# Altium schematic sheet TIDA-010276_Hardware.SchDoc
size 431 x 279 mm; Date: Not shown in title block; ApprovedBy: Not shown in title block; CheckedBy: Not shown in title block; Author: Not shown in title block; CompanyName: Not shown in title block; DrawnBy: Jenson Fang; Engineer: Jenson Fang; Organization: Not shown in title block; Address1: Not shown in title block; Address2: Not shown in title block; Address3: Not shown in title block; Address4: Not shown in title block; DocumentNumber: 3; Revision: Use project parameter SCH_Rev; SheetNumber: 6; SheetTotal: 6; PageSetup: Record=PageOptions¦CenterHorizontal=True¦CenterVertical=True¦PrintScale=1.00¦XCorrection=1.00¦YCorrection=1.00¦PrintKind=0¦BorderSize=5000000¦LeftOffset=0¦BottomOffset=0¦Orientation=2¦PaperLength=1000¦PaperWidth=1000¦Scale=100¦PaperSource=15¦PrintQuality=600¦MediaType=1¦DitherType=10¦PaperKind=Letter¦PrintScaleMode=1
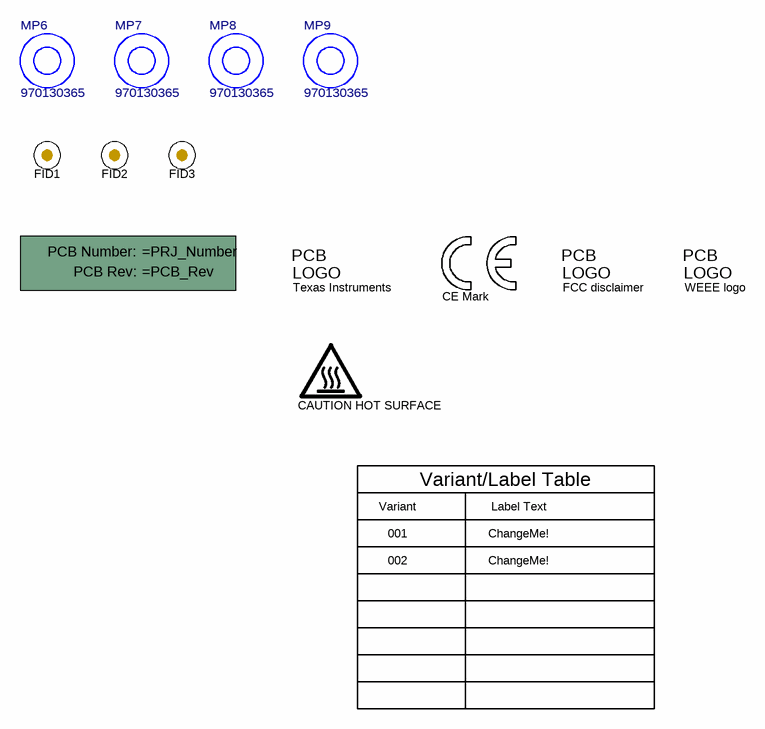
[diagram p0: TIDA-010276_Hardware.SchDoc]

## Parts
!PCB1  Printed Circuit Board  (value not drawn)  (mechanical)
FID1  Fiducial  [Fiducial10-20]  (value not drawn)
FID2  Fiducial  [Fiducial10-20]  (value not drawn)
FID3  Fiducial  [Fiducial10-20]  (value not drawn)
Logo1  CE Mark  [CE_Mark_5mm]  (no BOM)
Logo2  Texas Instruments  [TI_Stacked_Overlay_Small]  (no BOM)
Logo3  FCC disclaimer  [FCC_disclaimer]  (no BOM)
Logo4  WEEE logo  [WEEE_Minimum]  (no BOM)
LOGO5  CAUTION HOT SURFACE  [IEC_HotSurface_Small]  (no BOM)
MP6  970130365  [FP-970130365_SPCAER_M3-MFG]
MP7  970130365  [FP-970130365_SPCAER_M3-MFG]
MP8  970130365  [FP-970130365_SPCAER_M3-MFG]
MP9  970130365  [FP-970130365_SPCAER_M3-MFG]

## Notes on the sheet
- Variant
- Variant/Label Table
- Label Text
- 001
- 002
- ChangeMe!

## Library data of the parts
!PCB1 = CMP-0003618-2: Manufacturer: Any
FID1-FID3 = CMP-0077181-1: Fiducial mark.  There is nothing to buy or mount.
Logo1 = CMP-0074844-1: SymbolCreator: a0412235
Logo2 = CMP-0074838-1: Texas Instrument Corporate Signature; SymbolCreator: a0412235; Lib Reference: TI_Logo; Library Reference: Logo
Logo3 = CMP-0074847-1: FCC_disclaimer; Library Reference: Logo
Logo4 = CMP-0074769-1
LOGO5 = CMP-0074837-1: IEC 61010-1 Hot Surface Warning; SymbolCreator: a0412235; Lib Reference: IEC_HotSurface
MP6-MP9 = CMP-0087151-1: Manufacturer: Wurth Electronics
